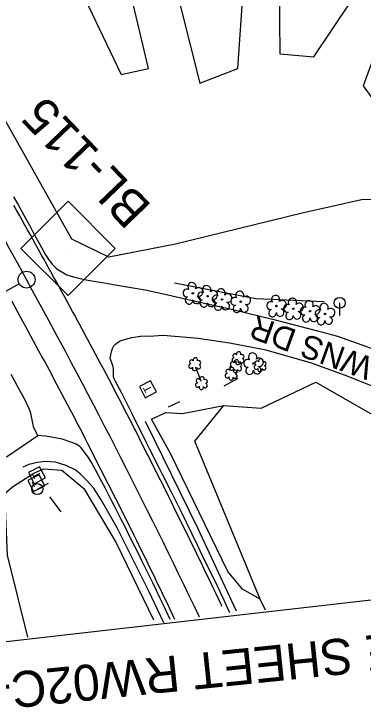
# Model space of a CAD drawing. Extents: x 474972 to 479313, y 498315 to 502691.
# Drawn here: x 477663.9 to 477818.9, y 499399.9 to 499710.1 of the extents above; entities that cross this region are included whole.
import ezdxf

# ---------------------------------------------------------------- set-up
doc = ezdxf.new("R2010")
doc.units = 0
for name, color, linetype in [('CTL Secondary Horizontal and Vertical CELL', 7, 'Continuous'), ('CTL Secondary Horizontal and Vertical Text', 7, 'Continuous'), ('Exist Guardrail', 7, 'Continuous'), ('Exist Horizontal Alignment', 7, 'Continuous'), ('Exist Other Culture Fence Line', 7, 'Continuous'), ('Exist Other Culture Sign', 7, 'Continuous'), ('Exist Roads EOP', 7, 'Continuous'), ('Exist Roads EOP Other', 7, 'Continuous'), ('Exist Roads EOP Text', 7, 'Continuous'), ('Exist Roads EOT', 7, 'Continuous'), ('Exist Utilities Power Pole CELL', 7, 'Continuous'), ('Exist Utilities Telephone Pedestal CELL', 7, 'Continuous'), ('Exist Vegetation Hedge Row', 7, 'Continuous'), ('Exist Vegetation Shrub CELL', 7, 'Continuous'), ('Exist Vegetation Tree CELL', 7, 'Continuous'), ('Exist Vegetation Woods Line', 7, 'Continuous'), ('Matchline', 7, 'Continuous'), ('Matchline Text', 7, 'Continuous')]:
    doc.layers.add(name, color=color, linetype=linetype)

msp = doc.modelspace()

# ---------------------------------------------------------------- linework, layer by layer
at = {"layer": 'CTL Secondary Horizontal and Vertical CELL'}
msp.add_line((477687.76, 499605.86), (477687.76, 499605.86), dxfattribs=at)
msp.add_lwpolyline([(477666.9, 499605.93), (477687.86, 499626.9), (477708.87, 499605.9), (477687.9, 499584.93)], close=True, dxfattribs=at)
at = {"layer": 'Exist Guardrail'}
for points in [[(477722.21, 499529.15), (477745.35, 499481.72), (477762.54, 499444.86)], [(477730.39, 499439.61), (477723.79, 499453.57), (477709.75, 499481.73), (477702.6, 499494.22), (477699.23, 499499.5), (477695.99, 499503.14), (477693.27, 499505.78), (477691.03, 499507.53), (477687.01, 499509.54), (477682.32, 499510.96), (477677.68, 499511.26), (477674.3, 499510.87), (477670.47, 499509.85), (477667.73, 499508.75)]]:
    msp.add_lwpolyline(points, dxfattribs=at)
at = {"layer": 'Exist Horizontal Alignment'}
msp.add_line((477666.17, 499590.25), (477560.97, 499532.45), dxfattribs=at)
msp.add_circle((477669.46, 499592.05), 3.75, dxfattribs=at)
for centre, radius, start, end in [((475221.34, 498247), 2793.29, 28.78535, 34.16531), ((475150.42, 498208.04), 2874.21, 25.42501, 28.78535)]:
    msp.add_arc(centre, radius, start, end, dxfattribs=at)
at = {"layer": 'Exist Other Culture Fence Line'}
msp.add_lwpolyline([(477735.2, 499590.62), (477771.33, 499583.73), (477801.65, 499582.32)], dxfattribs=at)
at = {"layer": 'Exist Other Culture Sign'}
for p, q in [((477744.48, 499553.38), (477746.82, 499546.96)), ((477763.24, 499548.17), (477757.11, 499544.66)), ((477737.39, 499537.78), (477732.34, 499535.35)), ((477679.58, 499495.48), (477684.66, 499488.91))]:
    msp.add_line(p, q, dxfattribs=at)
at = {"layer": 'Exist Roads EOP'}
for points in [[(477663.69, 499628.8), (477665.5, 499625.57), (477667.3, 499622.32), (477669.11, 499619.06), (477670.85, 499615.92), (477672.45, 499613.02), (477675.25, 499607.94), (477677.93, 499603.07), (477679.27, 499600.84), (477680.81, 499598.87), (477682.45, 499597.25), (477683.29, 499596.56), (477687.33, 499594.24), (477690.27, 499593.36), (477693.27, 499592.59), (477696.74, 499591.88), (477700.42, 499591.22), (477704.02, 499590.58), (477707.88, 499589.88)], [(477707.88, 499589.88), (477722.16, 499587.47), (477730.89, 499585.6), (477744.44, 499582.53), (477761.14, 499578.78), (477779.27, 499574.4), (477798.64, 499569.33), (477807.56, 499566.95), (477820.5, 499562.36), (477833.18, 499557.3), (477846.07, 499551.66), (477863.4, 499542.88), (477869.88, 499538.85), (477877.39, 499533.81), (477890.81, 499524.15), (477904.64, 499513.95), (477915.66, 499505.08), (477929.16, 499493.74), (477940.15, 499483.91), (477950.57, 499473.62), (477955.31, 499469.04)], [(477759.78, 499444.09), (477759.51, 499444.67), (477758.14, 499447.6), (477756.79, 499450.47), (477755.46, 499453.27), (477752.87, 499458.68), (477750.32, 499463.93), (477747.82, 499469.05), (477745.39, 499474.04), (477743.01, 499478.93), (477740.59, 499483.9), (477738.1, 499488.98), (477735.47, 499494.3), (477734.09, 499497.06), (477732.69, 499499.84), (477731.28, 499502.63), (477729.88, 499505.42), (477728.47, 499508.21), (477727.06, 499511), (477725.66, 499513.77), (477724.26, 499516.55), (477722.87, 499519.31), (477721.51, 499522.04), (477718.92, 499527.28), (477716.5, 499532.2), (477714.31, 499536.56), (477711.55, 499541.85), (477708.8, 499547.02), (477708.51, 499547.73), (477708.28, 499548.42), (477708.13, 499549.08), (477708.05, 499549.72), (477708.07, 499551.58), (477708.01, 499552.37), (477707.85, 499553.25), (477707.32, 499555.04), (477706.56, 499557), (477706.54, 499557.22), (477707.19, 499560.14), (477707.67, 499561.45), (477707.94, 499562.05), (477708.24, 499562.58), (477708.56, 499563.01), (477708.9, 499563.37), (477709.65, 499563.97), (477710.53, 499564.54), (477711.05, 499564.81), (477712.42, 499565.34), (477716.15, 499566.28), (477720.22, 499566.9)], [(477939.56, 499462.4), (477932.37, 499469.51), (477918.47, 499481.95), (477903.33, 499493.99), (477893.66, 499501.94), (477887.35, 499506.88), (477877.09, 499514.45), (477866.29, 499521.77), (477854.51, 499529.64), (477841.09, 499537.31), (477827.13, 499543.08), (477811.07, 499549.49), (477795.97, 499554.98), (477775.84, 499560.75), (477759.62, 499563.89), (477745.62, 499565.92), (477730.11, 499567.18), (477723.96, 499566.83), (477720.22, 499566.9)], [(477733.3, 499441.01), (477732.36, 499442.98), (477730.55, 499446.79), (477728.8, 499450.45), (477727.11, 499453.98), (477725.47, 499457.36), (477723.87, 499460.66), (477722.28, 499463.93), (477720.7, 499467.16), (477719.12, 499470.35), (477717.55, 499473.51), (477715.99, 499476.64), (477714.44, 499479.73), (477712.9, 499482.79), (477711.38, 499485.78), (477709.91, 499488.68), (477708.48, 499491.47), (477707.09, 499494.17), (477705.72, 499496.84), (477704.31, 499499.54), (477702.89, 499502.27), (477700.11, 499507.54), (477698.35, 499510.83), (477696.97, 499513.07), (477693.74, 499517.29), (477693.32, 499517.7), (477692.79, 499518.12), (477692.16, 499518.54), (477691.42, 499518.97), (477689.63, 499519.76), (477685.22, 499521.15), (477680.53, 499522.07), (477677.79, 499522.45), (477674.41, 499522.87), (477673.03, 499525.6), (477672.6, 499526.67), (477672.34, 499527.47), (477671.36, 499532.65), (477670.81, 499534.35), (477668.32, 499539.41), (477665.74, 499544.17), (477664.2, 499547.01), (477662.67, 499549.89)]]:
    msp.add_lwpolyline(points, dxfattribs=at)
at = {"layer": 'Exist Roads EOP Other'}
msp.add_line((477660.59, 499513.36), (477674.41, 499522.87), dxfattribs=at)
at = {"layer": 'Exist Roads EOT'}
for points in [[(477756.35, 499446.89), (477755.81, 499448), (477754.73, 499450.26), (477753.64, 499452.51), (477752.55, 499454.76), (477751.47, 499457.01), (477750.38, 499459.26), (477749.3, 499461.51), (477748.21, 499463.76), (477747.12, 499466.01), (477746.04, 499468.26), (477744.95, 499470.51), (477743.86, 499472.76), (477743.71, 499473.08), (477742.61, 499475.32), (477741.5, 499477.56), (477740.4, 499479.8), (477739.3, 499482.04), (477738.19, 499484.29), (477737.09, 499486.53), (477735.98, 499488.77), (477734.88, 499491.01), (477733.77, 499493.25), (477732.67, 499495.49), (477731.57, 499497.74), (477731.2, 499498.49), (477730.07, 499500.72), (477728.95, 499502.95), (477727.82, 499505.18), (477726.7, 499507.41), (477725.57, 499509.64), (477724.45, 499511.87), (477723.32, 499514.11), (477722.2, 499516.34), (477721.07, 499518.57), (477719.95, 499520.8), (477718.82, 499523.03), (477717.7, 499525.26), (477717.47, 499525.72), (477716.32, 499527.94), (477715.17, 499530.16), (477714.02, 499532.38), (477712.88, 499534.6), (477711.73, 499536.82), (477710.58, 499539.04), (477709.44, 499541.26), (477708.29, 499543.48), (477707.12, 499545.74), (477705.95, 499547.94), (477704.77, 499550.15), (477703.6, 499552.35), (477702.42, 499554.56), (477701.25, 499556.76), (477700.07, 499558.97), (477698.9, 499561.18), (477697.72, 499563.38), (477696.55, 499565.59), (477695.37, 499567.79), (477694.19, 499570), (477693.02, 499572.2), (477691.84, 499574.41), (477691.12, 499575.76), (477689.92, 499577.95), (477688.71, 499580.14), (477687.51, 499582.33), (477686.3, 499584.52), (477685.1, 499586.7), (477683.89, 499588.89), (477682.69, 499591.08), (477681.48, 499593.27), (477680.28, 499595.46), (477679.07, 499597.65), (477677.87, 499599.84), (477677.21, 499601.03), (477675.99, 499603.22), (477674.78, 499605.4), (477673.56, 499607.58), (477672.35, 499609.77), (477671.13, 499611.95), (477669.92, 499614.13), (477668.7, 499616.32), (477667.49, 499618.5), (477666.27, 499620.68), (477665.05, 499622.87), (477663.84, 499625.05)], [(477735.27, 499441.24), (477735.22, 499441.33), (477734.14, 499443.58), (477733.06, 499445.84), (477731.99, 499448.09), (477730.91, 499450.35), (477729.83, 499452.6), (477728.75, 499454.85), (477727.67, 499457.11), (477726.59, 499459.36), (477725.51, 499461.62), (477724.43, 499463.87), (477723.35, 499466.12), (477722.87, 499467.12), (477721.75, 499469.36), (477720.64, 499471.59), (477719.52, 499473.83), (477718.41, 499476.07), (477717.29, 499478.3), (477716.18, 499480.54), (477715.06, 499482.77), (477713.94, 499485.01), (477712.83, 499487.25), (477711.71, 499489.48), (477710.6, 499491.72), (477710.24, 499492.44), (477709.11, 499494.67), (477707.97, 499496.89), (477706.84, 499499.12), (477705.71, 499501.35), (477704.58, 499503.58), (477703.44, 499505.8), (477702.31, 499508.03), (477701.18, 499510.26), (477700.05, 499512.49), (477698.92, 499514.71), (477697.78, 499516.94), (477696.65, 499519.17), (477695.52, 499521.4), (477694.39, 499523.62), (477693.25, 499525.85), (477692.42, 499527.49), (477691.25, 499529.7), (477690.09, 499531.91), (477688.92, 499534.12), (477687.75, 499536.33), (477686.59, 499538.53), (477685.42, 499540.74), (477684.25, 499542.95), (477683.08, 499545.16), (477681.92, 499547.37), (477680.75, 499549.58), (477679.58, 499551.79), (477678.54, 499553.76), (477677.35, 499555.95), (477676.15, 499558.15), (477674.96, 499560.34), (477673.76, 499562.54), (477672.57, 499564.73), (477671.37, 499566.93), (477670.18, 499569.12), (477668.98, 499571.32), (477667.79, 499573.51), (477666.59, 499575.71), (477665.4, 499577.9), (477664.2, 499580.1), (477663, 499582.29)]]:
    msp.add_lwpolyline(points, dxfattribs=at)
at = {"layer": 'Exist Utilities Power Pole CELL'}
for p, q in [((477808.54, 499581.72), (477808.54, 499576.09)), ((477808.54, 499581.72), (477808.54, 499581.72)), ((477674.25, 499498.98), (477679.24, 499501.57)), ((477674.25, 499498.98), (477674.25, 499498.98))]:
    msp.add_line(p, q, dxfattribs=at)
for centre in [(477808.54, 499581.72), (477674.25, 499498.98)]:
    msp.add_circle(centre, 2.45, dxfattribs=at)
at = {"layer": 'Exist Utilities Telephone Pedestal CELL'}
for p, q in [((477723.36, 499543.26), (477723.36, 499543.26)), ((477674.05, 499505.06), (477674.05, 499505.06)), ((477673.85, 499501.55), (477673.85, 499501.55))]:
    msp.add_line(p, q, dxfattribs=at)
for points in [[(477727.12, 499542.15), (477724.54, 499547.11), (477719.57, 499544.52), (477722.16, 499539.56), (477727.12, 499542.15)], [(477677.81, 499503.92), (477675.26, 499508.9), (477670.28, 499506.35), (477672.83, 499501.37), (477677.81, 499503.92)], [(477677.59, 499500.38), (477675.09, 499505.38), (477670.08, 499502.88), (477672.59, 499497.87), (477677.59, 499500.38)]]:
    msp.add_lwpolyline(points, dxfattribs=at)
at = {"layer": 'Exist Vegetation Hedge Row'}
for points in [[(477773.29, 499450.05), (477765.36, 499454.51), (477758.8, 499462.34), (477733.43, 499514.87), (477724.96, 499530.03), (477731.39, 499533.02), (477738.67, 499532.54), (477757.06, 499536.14)], [(477659.61, 499496.91), (477663.15, 499499.97), (477672.75, 499506.09), (477677, 499508.06), (477685.17, 499507.4), (477694.96, 499499.27), (477709.22, 499475.04), (477725.82, 499440.87)]]:
    msp.add_lwpolyline(points, dxfattribs=at)
at = {"layer": 'Exist Vegetation Shrub CELL'}
for p, q in [((477763.48, 499556.97), (477763.48, 499556.97)), ((477744.22, 499554.3), (477744.22, 499554.3)), ((477762.41, 499553.41), (477762.41, 499553.41)), ((477773.27, 499553.84), (477773.27, 499553.84)), ((477760.4, 499550.06), (477760.4, 499550.06)), ((477747.2, 499545.9), (477747.2, 499545.9))]:
    msp.add_line(p, q, dxfattribs=at)
for centre, radius, start, end in [((477762, 499558.1), 0.968, 35.8908, 245.4216), ((477763.71, 499559.01), 0.99, 334.8391, 200.4717), ((477765.15, 499557.84), 0.929, 284.4567, 126.0861), ((477742.74, 499555.43), 0.968, 35.8908, 245.4216), ((477744.45, 499556.34), 0.99, 334.8391, 200.4717), ((477745.89, 499555.17), 0.929, 284.4567, 126.0861), ((477760.92, 499554.54), 0.968, 35.8908, 245.4216), ((477761.68, 499556.27), 0.955, 95.1099, 327.9534), ((477762.63, 499555.45), 0.99, 334.8391, 200.4717), ((477763.35, 499555.29), 0.984, 151.2797, 21.387), ((477764.08, 499554.28), 0.929, 284.4567, 126.0861), ((477765.12, 499556.04), 0.937, 204.9913, 73.4601), ((477771.79, 499554.96), 0.968, 35.8908, 245.4216), ((477773.5, 499555.88), 0.99, 334.8391, 200.4717), ((477774.94, 499554.71), 0.929, 284.4567, 126.0861), ((477742.42, 499553.6), 0.955, 95.1099, 327.9534), ((477744.09, 499552.62), 0.984, 151.2797, 21.387), ((477745.86, 499553.37), 0.937, 204.9913, 73.4601), ((477758.92, 499551.19), 0.968, 35.8908, 245.4216), ((477760.63, 499552.1), 0.99, 334.8391, 200.4717), ((477760.61, 499552.71), 0.955, 95.1099, 327.9534), ((477762.28, 499551.73), 0.984, 151.2797, 21.387), ((477764.04, 499552.48), 0.937, 204.9913, 73.4601), ((477771.47, 499553.13), 0.955, 95.1099, 327.9534), ((477773.14, 499552.15), 0.984, 151.2797, 21.387), ((477774.91, 499552.91), 0.937, 204.9913, 73.4601), ((477758.6, 499549.36), 0.955, 95.1099, 327.9534), ((477762.04, 499549.13), 0.937, 204.9913, 73.4601), ((477762.07, 499550.93), 0.929, 284.4567, 126.0861), ((477745.4, 499545.19), 0.955, 95.1099, 327.9534), ((477745.72, 499547.02), 0.968, 35.8908, 245.4216), ((477747.43, 499547.94), 0.99, 334.8391, 200.4717), ((477748.84, 499544.97), 0.937, 204.9913, 73.4601), ((477748.88, 499546.77), 0.929, 284.4567, 126.0861), ((477760.27, 499548.38), 0.984, 151.2797, 21.387), ((477747.08, 499544.21), 0.984, 151.2797, 21.387)]:
    msp.add_arc(centre, radius, start, end, dxfattribs=at)
at = {"layer": 'Exist Vegetation Tree CELL'}
for p, q in [((477743.32, 499586), (477743.32, 499586)), ((477749.85, 499584.68), (477749.85, 499584.68)), ((477756.26, 499583.24), (477756.26, 499583.24)), ((477764.55, 499582.24), (477764.55, 499582.24)), ((477780.45, 499580.33), (477780.45, 499580.33)), ((477787.96, 499579.12), (477787.96, 499579.12)), ((477795.37, 499578.01), (477795.37, 499578.01)), ((477802.01, 499576.79), (477802.01, 499576.79)), ((477770.23, 499554.76), (477770.23, 499554.76))]:
    msp.add_line(p, q, dxfattribs=at)
for centre in [(477743.32, 499586), (477749.85, 499584.68), (477756.26, 499583.24), (477764.55, 499582.24), (477780.45, 499580.33), (477787.96, 499579.12), (477795.37, 499578.01), (477802.01, 499576.79), (477770.23, 499554.76)]:
    msp.add_circle(centre, 0.326, dxfattribs=at)
for centre, radius, start, end in [((477742.94, 499588.88), 1.86, 330.1651, 219.7134), ((477749.46, 499587.55), 1.86, 330.1651, 219.7134), ((477740.72, 499586.16), 1.73, 62.6636, 279.3457), ((477745.87, 499586.59), 1.9, 257.1011, 134.1999), ((477747.24, 499584.83), 1.73, 62.6636, 279.3457), ((477752.39, 499585.26), 1.9, 257.1011, 134.1999), ((477755.87, 499586.11), 1.86, 330.1651, 219.7134), ((477764.17, 499585.12), 1.86, 330.1651, 219.7134), ((477741.62, 499582.88), 1.69, 111.5671, 6.231), ((477745, 499583.1), 1.7, 181.2822, 74.56), ((477748.14, 499581.55), 1.69, 111.5671, 6.231), ((477751.52, 499581.78), 1.7, 181.2822, 74.56), ((477753.65, 499583.39), 1.73, 62.6636, 279.3457), ((477758.81, 499583.83), 1.9, 257.1011, 134.1999), ((477761.95, 499582.4), 1.73, 62.6636, 279.3457), ((477767.1, 499582.83), 1.9, 257.1011, 134.1999), ((477780.06, 499583.21), 1.86, 330.1651, 219.7134), ((477787.58, 499581.99), 1.86, 330.1651, 219.7134), ((477754.55, 499580.12), 1.69, 111.5671, 6.231), ((477757.93, 499580.34), 1.7, 181.2822, 74.56), ((477762.85, 499579.12), 1.69, 111.5671, 6.231), ((477766.22, 499579.34), 1.7, 181.2822, 74.56), ((477777.84, 499580.49), 1.73, 62.6636, 279.3457), ((477782.99, 499580.92), 1.9, 257.1011, 134.1999), ((477785.36, 499579.27), 1.73, 62.6636, 279.3457), ((477790.51, 499579.71), 1.9, 257.1011, 134.1999), ((477794.99, 499580.88), 1.86, 330.1651, 219.7134), ((477797.92, 499578.6), 1.9, 257.1011, 134.1999), ((477801.62, 499579.67), 1.86, 330.1651, 219.7134), ((477778.74, 499577.21), 1.69, 111.5671, 6.231), ((477782.12, 499577.43), 1.7, 181.2822, 74.56), ((477786.26, 499576), 1.69, 111.5671, 6.231), ((477789.64, 499576.22), 1.7, 181.2822, 74.56), ((477792.77, 499578.16), 1.73, 62.6636, 279.3457), ((477799.4, 499576.95), 1.73, 62.6636, 279.3457), ((477804.55, 499577.38), 1.9, 257.1011, 134.1999), ((477793.67, 499574.89), 1.69, 111.5671, 6.231), ((477797.04, 499575.11), 1.7, 181.2822, 74.56), ((477800.3, 499573.67), 1.69, 111.5671, 6.231), ((477803.68, 499573.89), 1.7, 181.2822, 74.56), ((477769.85, 499557.63), 1.86, 330.1651, 219.7134), ((477767.63, 499554.91), 1.73, 62.6636, 279.3457), ((477772.78, 499555.35), 1.9, 257.1011, 134.1999), ((477768.53, 499551.64), 1.69, 111.5671, 6.231), ((477771.9, 499551.86), 1.7, 181.2822, 74.56)]:
    msp.add_arc(centre, radius, start, end, dxfattribs=at)
at = {"layer": 'Exist Vegetation Woods Line'}
for points in [[(477688.89, 499730.68), (477711.45, 499683.2), (477723.59, 499685.92), (477715.54, 499720.38)], [(477733.96, 499728.84), (477746.43, 499679.37), (477763.29, 499685.87), (477765.88, 499722.43)], [(477781.66, 499722.67), (477782.03, 499692.35), (477797.09, 499691.09), (477813.7, 499715.84)], [(477876.38, 499706.59), (477843.58, 499697.18), (477823.77, 499691.04), (477818.96, 499678.19), (477836.09, 499654.48), (477856.54, 499679.3), (477871.93, 499673.78), (477841.32, 499632.8), (477833.17, 499627.98), (477818.22, 499627.52), (477791.9, 499621.51), (477735.64, 499607.74), (477706, 499602.05), (477689.58, 499609.97), (477652.36, 499676.12)], [(477775.6, 499445.19), (477773.29, 499450.05), (477744.13, 499520.27), (477757.06, 499536.14), (477773.74, 499534.94), (477797.95, 499546.46), (477847.63, 499518.13), (477837.84, 499505.13), (477841.46, 499481.55), (477851.69, 499460.06)], [(477550.66, 499429.73), (477577.08, 499449.67), (477637.89, 499484.83), (477654.45, 499501.19), (477659.61, 499496.91), (477660.87, 499469.61), (477669.88, 499433.14)]]:
    msp.add_lwpolyline(points, dxfattribs=at)
at = {"layer": 'Matchline'}
msp.add_line((477986.93, 499468.27), (477490.12, 499411.83), dxfattribs=at)

# ---------------------------------------------------------------- texts
at = {"layer": 'CTL Secondary Horizontal and Vertical Text'}
msp.add_text('BL-115', height=16, rotation=133.8723, dxfattribs=at).set_placement((477725.51, 499624.7))
at = {"layer": 'Exist Roads EOP Text'}
msp.add_text('DOWNS DR', height=10.4, rotation=160.0879, dxfattribs=at).set_placement((477843.76, 499549.97))
at = {"layer": 'Exist Utilities Telephone Pedestal CELL'}
for rotation, p in [(117.5059, (477725.4, 499543.05)), (117.1144, (477676.09, 499504.83)), (116.5819, (477675.88, 499501.31))]:
    msp.add_text('T', height=3.42, rotation=rotation, dxfattribs=at).set_placement(p)
at = {"layer": 'Matchline Text'}
msp.add_text('MATCHLINE SHEET RW02C-4', height=16, rotation=185.8839, dxfattribs=at).set_placement((477942.29, 499446.41))

doc.saveas('drawing.dxf')
